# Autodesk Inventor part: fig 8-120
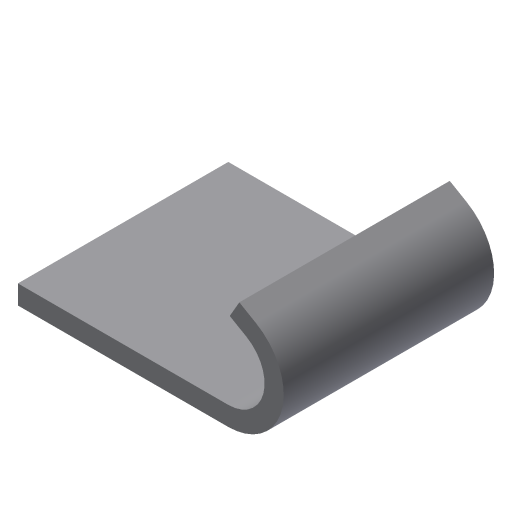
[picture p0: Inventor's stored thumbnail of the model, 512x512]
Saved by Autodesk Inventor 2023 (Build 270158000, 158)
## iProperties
Created: 2009-09
Part Number: fig 8-120
Document SubType Name: Modeling
Designer: Sham
Density: 1 g/cm^3
Material: Generic
Appearance: Default
Author: Sham
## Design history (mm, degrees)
sketch "Sketch1"
  geometry: L1 (-33.976, 22)-(0, 22); L2 (0, 22)-(0, 0); L3 (0, 0)-(-33.976, 0); L4 (-33.976, 0)-(-33.976, 22)
  constraints: 8 end point, 2 parallel, 1 horizontal, 1 perpendicular
extrude "Extrusion1" new body sketch "Sketch1" distance "d0" = 2; taper "d1" = 0 deg
sketch "Sketch2"
  geometry: L1 (-12, 22)-(-12, 0)
  constraints: 2 end point
feature "Bend Part1" sketch "Sketch2" dims "d4" = 10, "d5" = 150 deg
body "Solid1"
